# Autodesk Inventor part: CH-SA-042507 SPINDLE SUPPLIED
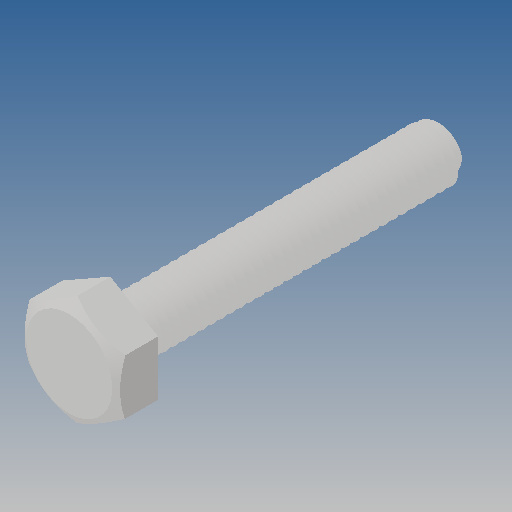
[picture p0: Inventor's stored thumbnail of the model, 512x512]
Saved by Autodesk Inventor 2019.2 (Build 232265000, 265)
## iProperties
Created: 2012-09
Part Number: CH-SA-042507 SPINDLE SUPPLIED
Material: Ogólny
Document SubType Name: Modeling
Designer: CADENGINEERING4
Density: 1 g/cm^3
Appearance: Domyślna
Author: CADENGINEERING4
Revision Number: ÈÎºÎ
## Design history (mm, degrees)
feature "ÇÐ³ý-É¨Ãè3"
node "Bryła1"
